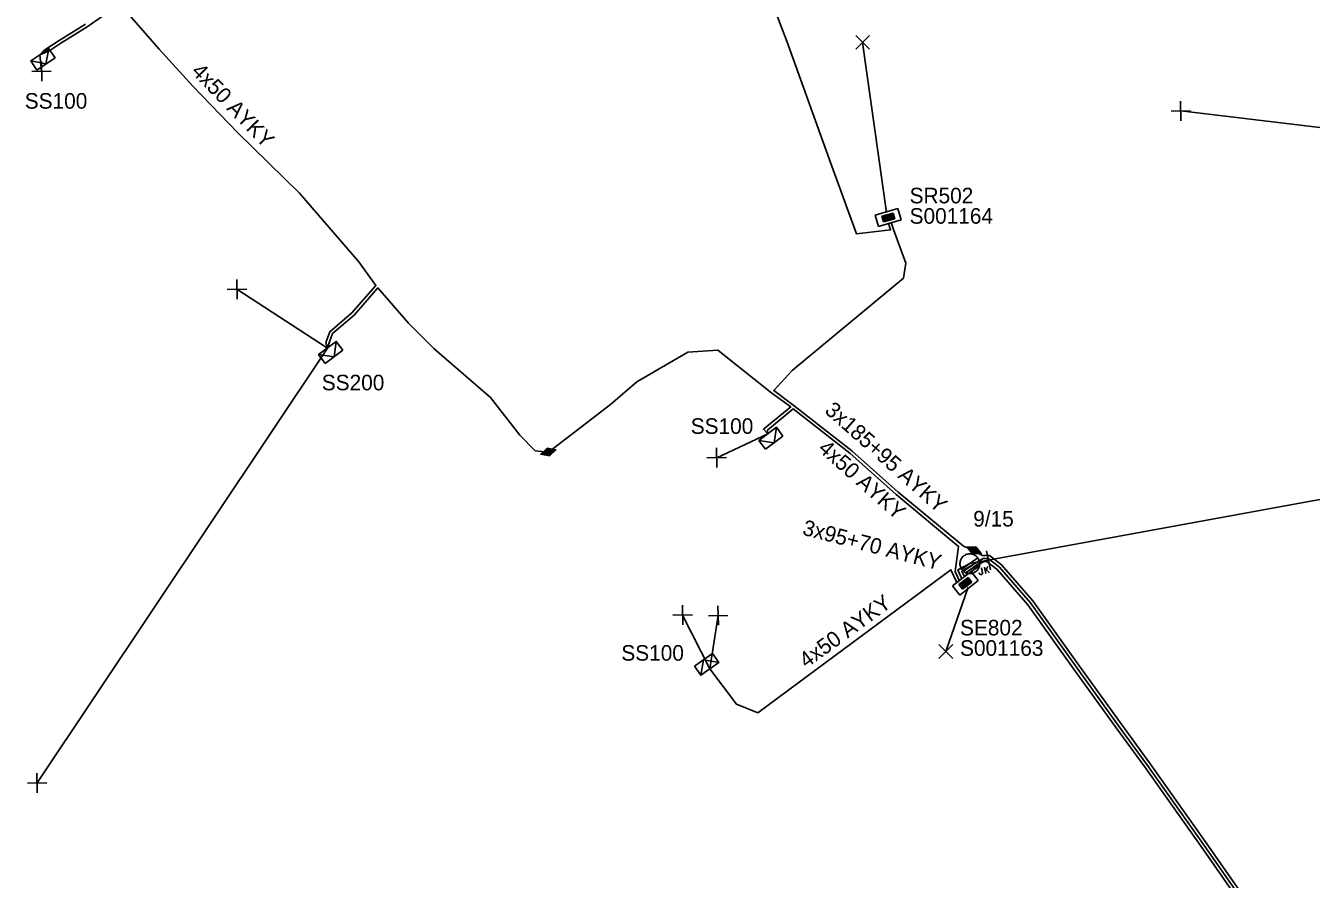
# Model space of a CAD drawing. Extents: x -762504 to -761250, y -1152974 to -1152253.
# Drawn here: x -761617.4 to -761535.4, y -1152553 to -1152498.6 of the extents above; entities that cross this region are included whole.
import ezdxf

# ---------------------------------------------------------------- set-up
doc = ezdxf.new("R2010")
doc.units = 0
for name, color, linetype in [('Vrstva 1', 7, 'Continuous'), ('Vrstva 12', 7, 'Continuous'), ('Vrstva 13', 7, 'Continuous'), ('Vrstva 18', 7, 'Continuous'), ('Vrstva 19', 7, 'Continuous'), ('Vrstva 28', 7, 'Continuous'), ('Vrstva 29', 7, 'Continuous'), ('Vrstva 30', 7, 'Continuous'), ('Vrstva 31', 7, 'Continuous'), ('Vrstva 33', 7, 'Continuous'), ('Vrstva 34', 7, 'Continuous'), ('Vrstva 5', 7, 'Continuous'), ('Vrstva 59', 7, 'Continuous'), ('Vrstva 6', 7, 'Continuous')]:
    doc.layers.add(name, color=color, linetype=linetype)

msp = doc.modelspace()

# ---------------------------------------------------------------- linework, layer by layer
at = {"layer": 'Vrstva 1'}
msp.add_lwpolyline([(-761495.14, -1152528.56), (-761527.14, -1152527.39), (-761557.16, -1152532.89)], dxfattribs=at)
at = {"layer": 'Vrstva 13'}
for points in [[(-761556.641, -1152532.531), (-761556.681, -1152532.479), (-761556.727, -1152532.432), (-761556.778, -1152532.389), (-761556.832, -1152532.352), (-761556.89, -1152532.321), (-761556.952, -1152532.297), (-761557.015, -1152532.279), (-761557.08, -1152532.267), (-761557.146, -1152532.262), (-761557.212, -1152532.265), (-761557.277, -1152532.274), (-761557.341, -1152532.29), (-761557.403, -1152532.313), (-761557.462, -1152532.341), (-761557.518, -1152532.376), (-761557.57, -1152532.417), (-761557.617, -1152532.463), (-761557.66, -1152532.513), (-761557.697, -1152532.568), (-761557.728, -1152532.626), (-761557.752, -1152532.687), (-761557.771, -1152532.751), (-761557.782, -1152532.816), (-761557.787, -1152532.881), (-761557.784, -1152532.947), (-761557.775, -1152533.012), (-761557.759, -1152533.076), (-761557.737, -1152533.139), (-761557.708, -1152533.198), (-761557.673, -1152533.254), (-761557.632, -1152533.306), (-761557.586, -1152533.353), (-761557.536, -1152533.395), (-761557.481, -1152533.432), (-761557.423, -1152533.463), (-761557.362, -1152533.488), (-761557.299, -1152533.506), (-761557.234, -1152533.518), (-761557.168, -1152533.522), (-761557.102, -1152533.52), (-761557.036, -1152533.511), (-761556.973, -1152533.495), (-761556.911, -1152533.472), (-761556.851, -1152533.443), (-761556.796, -1152533.408), (-761556.743, -1152533.368), (-761556.696, -1152533.322), (-761556.654, -1152533.271), (-761556.617, -1152533.217), (-761556.586, -1152533.159), (-761556.561, -1152533.097), (-761556.543, -1152533.034), (-761556.532, -1152532.969), (-761556.527, -1152532.903), (-761556.529, -1152532.837), (-761556.538, -1152532.772), (-761556.554, -1152532.708), (-761556.577, -1152532.646), (-761556.606, -1152532.587), (-761556.641, -1152532.531)], [(-761557.677, -1152533.251), (-761556.645, -1152532.529)], [(-761557.551, -1152533.379), (-761556.591, -1152532.708)], [(-761557.394, -1152533.45), (-761556.563, -1152532.868)], [(-761557.196, -1152533.492), (-761556.599, -1152533.074)]]:
    msp.add_lwpolyline(points, dxfattribs=at)
at = {"layer": 'Vrstva 18'}
for points in [[(-761556.096, -1152532.064), (-761555.836, -1152533.287)], [(-761556.417, -1152533.159), (-761556.349, -1152533.477)], [(-761556.214, -1152533.116), (-761556.128, -1152533.52)], [(-761556.161, -1152533.366), (-761556.012, -1152533.073)], [(-761556.111, -1152533.27), (-761555.893, -1152533.47)], [(-761556.551, -1152533.519), (-761556.561, -1152533.471)], [(-761556.526, -1152533.569), (-761556.551, -1152533.519)], [(-761556.446, -1152533.588), (-761556.526, -1152533.569)], [(-761556.417, -1152533.582), (-761556.446, -1152533.588)], [(-761556.357, -1152533.534), (-761556.417, -1152533.582)], [(-761556.349, -1152533.477), (-761556.357, -1152533.534)]]:
    msp.add_lwpolyline(points, dxfattribs=at)
at = {"layer": 'Vrstva 19'}
for points in [[(-761583.99, -1152526.011), (-761583.579, -1152525.631), (-761584.128, -1152525.53), (-761584.541, -1152525.907), (-761583.99, -1152526.011)], [(-761583.703, -1152525.671), (-761584.111, -1152525.591), (-761584.408, -1152525.869), (-761584.008, -1152525.95), (-761583.703, -1152525.671)], [(-761583.824, -1152525.705), (-761584.094, -1152525.652), (-761584.301, -1152525.842), (-761584.025, -1152525.89), (-761583.824, -1152525.705)], [(-761583.941, -1152525.739), (-761584.076, -1152525.712), (-761584.184, -1152525.808), (-761584.043, -1152525.829), (-761583.941, -1152525.739)], [(-761556.986, -1152532.268), (-761556.426, -1152532.25), (-761556.774, -1152531.814), (-761557.332, -1152531.828), (-761556.986, -1152532.268)], [(-761556.545, -1152532.199), (-761556.801, -1152531.871), (-761557.207, -1152531.886), (-761556.959, -1152532.21), (-761556.545, -1152532.199)], [(-761556.66, -1152532.146), (-761556.828, -1152531.929), (-761557.109, -1152531.936), (-761556.932, -1152532.153), (-761556.66, -1152532.146)], [(-761556.77, -1152532.094), (-761556.854, -1152531.986), (-761556.999, -1152531.988), (-761556.906, -1152532.096), (-761556.77, -1152532.094)]]:
    msp.add_lwpolyline(points, dxfattribs=at)
at = {"layer": 'Vrstva 28'}
for points in [[(-761561.747, -1152510.236), (-761563.189, -1152510.65)], [(-761561.54, -1152510.957), (-761561.747, -1152510.236)], [(-761563.189, -1152510.65), (-761562.982, -1152511.371)], [(-761562.982, -1152511.371), (-761561.54, -1152510.957)], [(-761562.052, -1152510.52), (-761562.768, -1152510.726)], [(-761562.768, -1152510.726), (-761562.664, -1152511.089)], [(-761562.085, -1152510.579), (-761562.709, -1152510.758)], [(-761562.709, -1152510.758), (-761562.631, -1152511.03)], [(-761562.664, -1152511.089), (-761561.948, -1152510.884)], [(-761562.117, -1152510.637), (-761562.651, -1152510.79)], [(-761562.651, -1152510.79), (-761562.599, -1152510.972)], [(-761562.631, -1152511.03), (-761562.007, -1152510.851)], [(-761562.599, -1152510.972), (-761562.065, -1152510.819)], [(-761562.15, -1152510.696), (-761562.592, -1152510.823)], [(-761562.592, -1152510.823), (-761562.566, -1152510.914)], [(-761562.566, -1152510.914), (-761562.124, -1152510.787)], [(-761562.176, -1152510.753), (-761562.54, -1152510.857)], [(-761562.124, -1152510.787), (-761562.15, -1152510.696)], [(-761562.065, -1152510.819), (-761562.117, -1152510.637)], [(-761562.007, -1152510.851), (-761562.085, -1152510.579)], [(-761561.948, -1152510.884), (-761562.052, -1152510.52)], [(-761557.079, -1152533.384), (-761558.262, -1152534.308)], [(-761556.618, -1152533.975), (-761557.079, -1152533.384)], [(-761557.269, -1152533.765), (-761557.856, -1152534.223)], [(-761557.8, -1152534.899), (-761556.618, -1152533.975)], [(-761557.277, -1152533.831), (-761557.789, -1152534.231)], [(-761557.285, -1152533.897), (-761557.723, -1152534.239)], [(-761557.294, -1152533.964), (-761557.657, -1152534.247)], [(-761557.623, -1152534.521), (-761557.037, -1152534.063)], [(-761557.615, -1152534.454), (-761557.103, -1152534.054)], [(-761557.607, -1152534.388), (-761557.169, -1152534.046)], [(-761557.598, -1152534.322), (-761557.235, -1152534.038)], [(-761557.595, -1152534.259), (-761557.297, -1152534.026)], [(-761557.235, -1152534.038), (-761557.294, -1152533.964)], [(-761557.169, -1152534.046), (-761557.285, -1152533.897)], [(-761557.103, -1152534.054), (-761557.277, -1152533.831)], [(-761557.037, -1152534.063), (-761557.269, -1152533.765)], [(-761558.262, -1152534.308), (-761557.8, -1152534.899)], [(-761557.856, -1152534.223), (-761557.623, -1152534.521)], [(-761557.789, -1152534.231), (-761557.615, -1152534.454)], [(-761557.723, -1152534.239), (-761557.607, -1152534.388)], [(-761557.657, -1152534.247), (-761557.598, -1152534.322)]]:
    msp.add_lwpolyline(points, dxfattribs=at)
at = {"layer": 'Vrstva 31'}
for points in [[(-761616.711, -1152501.394), (-761617.102, -1152500.813), (-761615.942, -1152500.031), (-761615.55, -1152500.611)], [(-761616.131, -1152501.002), (-761615.942, -1152500.031)], [(-761616.131, -1152501.002), (-761617.102, -1152500.813)], [(-761616.711, -1152501.394), (-761615.55, -1152500.611)], [(-761598.3, -1152520.112), (-761598.721, -1152519.553), (-761597.603, -1152518.711), (-761597.182, -1152519.27)], [(-761598.3, -1152520.112), (-761597.182, -1152519.27)], [(-761597.741, -1152519.691), (-761597.603, -1152518.711)], [(-761597.741, -1152519.691), (-761598.721, -1152519.553)], [(-761570.2, -1152525.592), (-761570.621, -1152525.033), (-761569.503, -1152524.191), (-761569.082, -1152524.75)], [(-761569.641, -1152525.171), (-761569.503, -1152524.191)], [(-761569.641, -1152525.171), (-761570.621, -1152525.033)], [(-761570.2, -1152525.592), (-761569.082, -1152524.75)], [(-761573.586, -1152538.633), (-761574.733, -1152539.436)], [(-761573.586, -1152538.633), (-761573.184, -1152539.207), (-761574.331, -1152540.01), (-761574.733, -1152539.436)], [(-761574.159, -1152539.035), (-761574.331, -1152540.01)], [(-761574.159, -1152539.035), (-761573.184, -1152539.207)]]:
    msp.add_lwpolyline(points, dxfattribs=at)
at = {"layer": 'Vrstva 34'}
for points in [[(-761564.442, -1152499.188), (-761563.558, -1152500.072)], [(-761564.442, -1152500.072), (-761563.558, -1152499.188)], [(-761616.399, -1152502.095), (-761616.421, -1152500.845)], [(-761617.035, -1152501.481), (-761615.785, -1152501.459)], [(-761543.679, -1152504.625), (-761543.701, -1152503.375)], [(-761544.315, -1152504.011), (-761543.065, -1152503.989)], [(-761603.929, -1152516.005), (-761603.951, -1152514.755)], [(-761604.565, -1152515.391), (-761603.315, -1152515.369)], [(-761573.299, -1152526.755), (-761573.321, -1152525.505)], [(-761573.935, -1152526.141), (-761572.685, -1152526.119)], [(-761575.479, -1152536.795), (-761575.501, -1152535.545)], [(-761573.209, -1152536.825), (-761573.231, -1152535.575)], [(-761576.115, -1152536.181), (-761574.865, -1152536.159)], [(-761573.845, -1152536.211), (-761572.595, -1152536.189)], [(-761559.132, -1152538.058), (-761558.248, -1152538.942)], [(-761559.132, -1152538.942), (-761558.248, -1152538.058)], [(-761616.679, -1152547.505), (-761616.701, -1152546.255)], [(-761617.315, -1152546.891), (-761616.065, -1152546.869)]]:
    msp.add_lwpolyline(points, dxfattribs=at)
at = {"layer": 'Vrstva 5'}
for points in [[(-761562.35, -1152511.19), (-761562.21, -1152511.6), (-761564.38, -1152511.85), (-761566.14, -1152507.05), (-761568.84, -1152499.56), (-761572.71, -1152489.44), (-761574.51, -1152484.19), (-761573.48, -1152483.9), (-761573.16, -1152483.71), (-761573.51, -1152483.7), (-761574.58, -1152484), (-761577.71, -1152476.35), (-761580.92, -1152468.65), (-761580.38, -1152468.69), (-761579.98, -1152468.63), (-761580.38, -1152468.49), (-761581.01, -1152468.44), (-761585.25, -1152459.23), (-761586.34, -1152455.49), (-761586.73, -1152453.58), (-761584.41, -1152452.04), (-761580.4, -1152450.51), (-761580.3, -1152451.05)], [(-761613.61, -1152498.47), (-761615.28, -1152499.51), (-761616.27, -1152500.14), (-761616.52, -1152500.42), (-761615.89, -1152500.14), (-761615.18, -1152499.69), (-761613.5, -1152498.63), (-761611.42, -1152497.19), (-761608.9, -1152500.06), (-761606.75, -1152502.42), (-761603.88, -1152505.41), (-761599.95, -1152509.26), (-761596.16, -1152513.64), (-761595.07, -1152515.14), (-761596.6, -1152516.89), (-761598.01, -1152518.09), (-761598.26, -1152518.77), (-761598.16, -1152519.13), (-761598.06, -1152518.81), (-761597.84, -1152518.21), (-761596.46, -1152517.03), (-761594.94, -1152515.3), (-761592.98, -1152517.55), (-761591.37, -1152519.17), (-761589.48, -1152520.81), (-761587.75, -1152522.29), (-761585.89, -1152524.7), (-761584.9, -1152525.7), (-761584.06, -1152525.77)], [(-761556.88, -1152532.04), (-761557.56, -1152531.78), (-761561.73, -1152528.32), (-761564.69, -1152525.69), (-761568.37, -1152522.81), (-761569.67, -1152521.85), (-761568.5, -1152520.56), (-761561.39, -1152514.67), (-761561.25, -1152513.71), (-761562.02, -1152511.56), (-761562.17, -1152511.13)], [(-761584.06, -1152525.77), (-761580.09, -1152522.73), (-761578.41, -1152521.28), (-761575.15, -1152519.39), (-761573.25, -1152519.26), (-761569.79, -1152522.01), (-761568.59, -1152522.89), (-761570.33, -1152524.31), (-761570.06, -1152524.61), (-761570.07, -1152524.37), (-761568.43, -1152523.02), (-761564.81, -1152525.85), (-761561.86, -1152528.48), (-761557.87, -1152531.79), (-761558.09, -1152533.4), (-761557.83, -1152533.97)], [(-761537.6, -1152557.44), (-761542.24, -1152550.81), (-761545.85, -1152545.71), (-761547.66, -1152543.24), (-761550.42, -1152539.41), (-761553.29, -1152535.39), (-761555.27, -1152533.11), (-761555.98, -1152532.57), (-761556.31, -1152532.56), (-761557.66, -1152533.37), (-761557.5, -1152533.73)], [(-761537.44, -1152557.33), (-761542.08, -1152550.7), (-761545.69, -1152545.59), (-761547.5, -1152543.12), (-761550.26, -1152539.29), (-761553.13, -1152535.27), (-761555.13, -1152532.96), (-761555.91, -1152532.37), (-761556.36, -1152532.36), (-761556.88, -1152532.04)], [(-761557.99, -1152534.09), (-761558.36, -1152533.28), (-761567.56, -1152540.09), (-761570.68, -1152542.4), (-761572.05, -1152541.85), (-761573.76, -1152539.61)], [(-761557.67, -1152533.85), (-761557.92, -1152533.29), (-761557.16, -1152532.89)], [(-761537.83, -1152557.47), (-761542.4, -1152550.93), (-761546.01, -1152545.83), (-761547.82, -1152543.36), (-761550.58, -1152539.53), (-761553.45, -1152535.51), (-761555.41, -1152533.26), (-761556.05, -1152532.77), (-761556.26, -1152532.76), (-761557.41, -1152533.45), (-761557.34, -1152533.6)]]:
    msp.add_lwpolyline(points, dxfattribs=at)
at = {"layer": 'Vrstva 59'}
for points in [[(-761562.47, -1152510.49), (-761564, -1152499.63)], [(-761616.52, -1152500.42), (-761616.41, -1152501.47)], [(-761532.16, -1152505.38), (-761543.69, -1152504)], [(-761598.16, -1152519.13), (-761603.94, -1152515.38)], [(-761598.16, -1152519.13), (-761616.69, -1152546.88)], [(-761570.06, -1152524.61), (-761573.31, -1152526.13)], [(-761557.27, -1152534.39), (-761558.69, -1152538.5)], [(-761573.76, -1152539.61), (-761575.49, -1152536.17)], [(-761573.76, -1152539.61), (-761573.22, -1152536.2)]]:
    msp.add_lwpolyline(points, dxfattribs=at)

# ---------------------------------------------------------------- texts
at = {"layer": 'Vrstva 12'}
msp.add_text('9/15', height=0.9943, dxfattribs=at).set_placement((-761556.94, -1152530.52))
at = {"layer": 'Vrstva 29'}
for s, p in [('S001164', (-761561, -1152511.2)), ('S001163', (-761557.78, -1152538.77))]:
    msp.add_text(s, height=0.9943, dxfattribs=at).set_placement(p)
at = {"layer": 'Vrstva 30'}
for s, p in [('SR502', (-761561, -1152509.9)), ('SE802', (-761557.78, -1152537.47))]:
    msp.add_text(s, height=0.9943, dxfattribs=at).set_placement(p)
at = {"layer": 'Vrstva 33'}
for s, p in [('SS100', (-761617.48, -1152503.86)), ('SS200', (-761598.52, -1152521.83)), ('SS100', (-761574.97, -1152524.61)), ('SS100', (-761579.4, -1152539.08))]:
    msp.add_text(s, height=0.9943, dxfattribs=at).set_placement(p)
at = {"layer": 'Vrstva 6'}
for s, height, rotation, p in [('4x50 AYKY', 0.9943, 313.98781, (-761606.9, -1152501.54)), ('3x185+95 AYKY', 0.99429, 318.37727, (-761566.48, -1152523.21)), ('4x50 AYKY', 0.9943, 318.37968, (-761566.9, -1152525.64)), ('3x95+70 AYKY', 0.99428, 345.38746, (-761567.9, -1152531.03)), ('4x50 AYKY', 0.9943, 35.97664, (-761567.59, -1152539.59))]:
    msp.add_text(s, height=height, rotation=rotation, dxfattribs=at).set_placement(p)

doc.saveas('drawing.dxf')
